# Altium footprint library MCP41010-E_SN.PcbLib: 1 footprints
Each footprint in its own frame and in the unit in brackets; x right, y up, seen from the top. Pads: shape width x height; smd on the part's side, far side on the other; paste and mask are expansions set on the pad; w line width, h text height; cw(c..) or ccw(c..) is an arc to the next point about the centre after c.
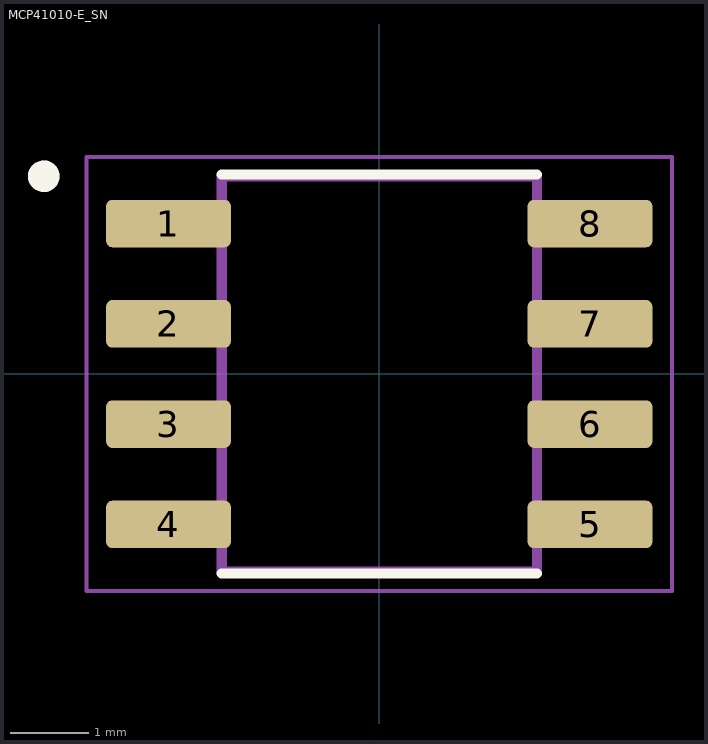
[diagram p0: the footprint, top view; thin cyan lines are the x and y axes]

## MCP41010-E_SN [mm]
pads (8):
  rrect25% 1.58x0.6 smd: 1(-2.67,1.905) 2(-2.67,0.635) 3(-2.67,-0.635) 4(-2.67,-1.905) 5(2.67,-1.905) 6(2.67,-0.635) 7(2.67,0.635) 8(2.67,1.905)
Top Overlay:
  circle w0.2: c-4.25,2.505 r0.1
  lines w0.127: -1.995,-2.525 1.995,-2.525 ; -1.995,2.525 1.995,2.525
Mechanical 13:
  circle w0.2: c-4.25,2.505 r0.1
  lines w0.127: -1.995,-2.5 -1.995,2.5 1.995,2.5 1.995,-2.5 -1.995,-2.5
Mechanical 15:
  lines w0.05: -3.71,-2.75 -3.71,2.75 3.71,2.75 3.71,-2.75 -3.71,-2.75
3D body "MCP41010-E_SN.STEP": height 1.75, standoff 0, extent -3,-2.45 3,2.45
